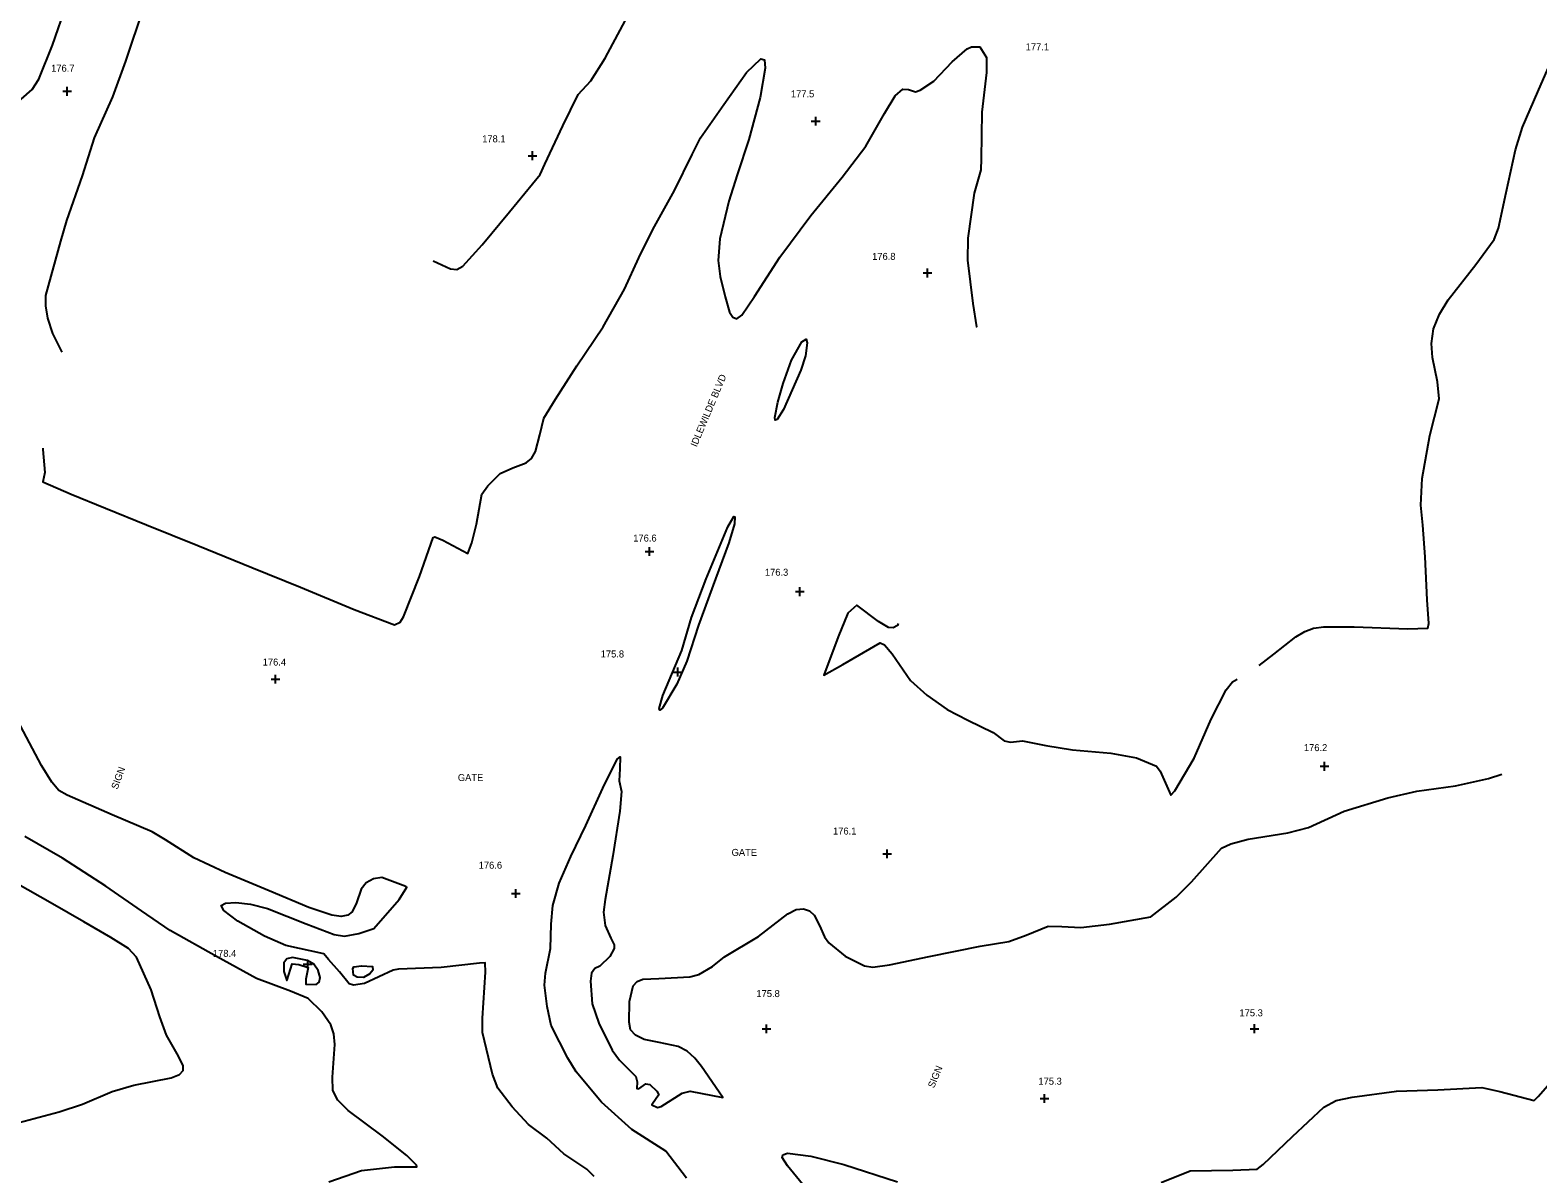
# Model space of a CAD drawing. Extents: x 1467615 to 2003689, y 770235 to 1108726.
# Drawn here: x 1997129.8 to 1997561.1, y 776158.5 to 776485.6 of the extents above; entities that cross this region are included whole.
import ezdxf

# ---------------------------------------------------------------- set-up
doc = ezdxf.new("R2010")
doc.units = 0
for name, color, linetype in [('RD_DTM_Major1', 7, 'Continuous'), ('RD_DTM_Minor1', 7, 'Continuous'), ('RD_DTM_Spot_Elev', 7, 'Continuous'), ('RD_TX_Misc1', 7, 'Continuous')]:
    doc.layers.add(name, color=color, linetype=linetype)

msp = doc.modelspace()

# ---------------------------------------------------------------- linework, layer by layer
at = {"layer": 'RD_DTM_Major1'}
for points in [[(1997453.38, 776156.03), (1997461.66, 776159.38), (1997473.82, 776159.52), (1997480.8, 776159.8), (1997482.56, 776161.17), (1997490.9, 776169.14), (1997499.88, 776177.51), (1997503.42, 776179.5), (1997508.01, 776180.4), (1997520.68, 776182.12), (1997532.49, 776182.47), (1997545.09, 776183.14), (1997550.2, 776182), (1997560, 776179.46), (1997561.18, 776180.58), (1997567.24, 776187.59), (1997569.53, 776189.42), (1997574.48, 776191.66), (1997584.08, 776194.29)], [(1997354.15, 776151.35), (1997346.5, 776160.76), (1997344.91, 776163.13), (1997345.11, 776163.96), (1997346.48, 776164.35), (1997353.14, 776163.53), (1997362.62, 776161.17), (1997377.91, 776156.18)]]:
    msp.add_lwpolyline(points, dxfattribs=at)
at = {"layer": 'RD_DTM_Minor1'}
for points in [[(1997286.62, 776467.18), (1997290.23, 776471.12), (1997294.31, 776477.55), (1997302.2, 776492.37), (1997309.65, 776506.51), (1997313.41, 776514.39), (1997315.15, 776520.48), (1997315.7, 776526.34), (1997315.67, 776530.4), (1997315.28, 776532.17), (1997314.46, 776533.54), (1997311.48, 776535), (1997308.11, 776536.27), (1997304.64, 776538.75), (1997301.04, 776540.1), (1997294.91, 776541.22), (1997293.99, 776541.28)], [(1997124.86, 776463.78), (1997130.45, 776468.61), (1997132.32, 776471.57), (1997136.22, 776481.27), (1997140.31, 776493.1)], [(1997162.25, 776492.06), (1997157.13, 776476.73), (1997153.41, 776466.58), (1997148.14, 776454.85), (1997144.74, 776443.91), (1997140.2, 776431.16), (1997138.57, 776425.27), (1997134.24, 776409.69), (1997134.25, 776406.77), (1997134.83, 776403.21), (1997136.28, 776398.84), (1997138.93, 776393.49)], [(1997133.44, 776366.01), (1997133.47, 776365.69), (1997134.07, 776359.08), (1997133.52, 776356.37), (1997141.61, 776352.86), (1997151.35, 776348.88), (1997163.16, 776344.1), (1997177.79, 776338.2), (1997193.25, 776331.94), (1997207.18, 776326.25), (1997222.48, 776319.91), (1997234.1, 776315.5), (1997235.72, 776316.27), (1997236.67, 776317.79), (1997241.19, 776329.31), (1997245.07, 776340.49), (1997245.58, 776340.64), (1997247.86, 776339.76), (1997255.08, 776335.88), (1997256.18, 776338.92), (1997257.47, 776344.26), (1997259, 776352.88), (1997260.77, 776355.23), (1997264.31, 776358.76), (1997267.87, 776360.45), (1997271.7, 776361.81), (1997273.26, 776363.1), (1997274.39, 776365.06), (1997275.65, 776369.86), (1997276.77, 776374.65), (1997280.07, 776380.09), (1997286.17, 776389.57), (1997293.76, 776400.78), (1997299.81, 776411.55), (1997303.93, 776420.44), (1997307.95, 776428.6), (1997314.11, 776439.7), (1997319.2, 776450.04), (1997321.54, 776454.77), (1997328.24, 776464.32), (1997334.74, 776473.47), (1997338.79, 776477.42), (1997339.9, 776477.1), (1997340.1, 776474.69), (1997338.67, 776466.32), (1997335.42, 776454.31), (1997332.08, 776444.18), (1997329.64, 776436.72), (1997327.15, 776425.93), (1997326.62, 776419.72), (1997327.17, 776415.17), (1997328.66, 776409.34), (1997329.86, 776404.97), (1997330.81, 776403.47), (1997332, 776403.07), (1997333.44, 776404.1), (1997337.05, 776409.43), (1997344.23, 776420.66), (1997353.14, 776432.55), (1997362.13, 776443.59), (1997368.84, 776452.47), (1997374.25, 776461.8), (1997377.22, 776466.82), (1997379.41, 776468.77), (1997381.04, 776468.68), (1997383.07, 776468.01), (1997384.45, 776468.49), (1997388.33, 776471.06), (1997393.55, 776476.56), (1997397.83, 776480.23), (1997399.06, 776480.84), (1997401.51, 776480.84), (1997403.34, 776477.78), (1997403.34, 776473.5), (1997402.08, 776462.13), (1997401.9, 776448.83), (1997401.77, 776445.61), (1997399.86, 776438.96), (1997398, 776426.15), (1997397.98, 776419.82), (1997399.43, 776407.45), (1997400.57, 776400.78), (1997400.63, 776400.66)], [(1997481.35, 776303.87), (1997485.57, 776307.08), (1997491.85, 776312.07), (1997494.43, 776313.65), (1997496.94, 776314.57), (1997499.85, 776314.98), (1997508.58, 776314.96), (1997523.87, 776314.35), (1997529.66, 776314.53), (1997529.86, 776315.89), (1997529.41, 776322.7), (1997528.81, 776334.99), (1997528.15, 776344.04), (1997527.62, 776349.77), (1997528.02, 776357.36), (1997530.17, 776369.66), (1997532.88, 776380.2), (1997532.41, 776385.02), (1997530.99, 776391.94), (1997530.71, 776395.96), (1997531.27, 776400.16), (1997532.94, 776404.4), (1997535.41, 776408.52), (1997543.31, 776418.6), (1997548.55, 776425.72), (1997549.78, 776429), (1997551.99, 776439.16), (1997554.69, 776451.4), (1997556.65, 776457.87), (1997561.05, 776468), (1997566.98, 776481.47)], [(1997245.13, 776419.63), (1997250.1, 776417.34), (1997251.89, 776417.18), (1997253.6, 776418.14), (1997259.09, 776424.17), (1997266.99, 776433.61), (1997275.68, 776444.34), (1997277.01, 776447.24), (1997282.22, 776458.21), (1997286.62, 776467.18)], [(1997345.18, 776384.57), (1997347.6, 776391.21), (1997350.52, 776396.42), (1997351.8, 776397.27), (1997352.06, 776396.14), (1997351.6, 776392.49), (1997350.24, 776388.31), (1997345.35, 776377.06), (1997343.49, 776374.24), (1997342.95, 776374.03), (1997342.8, 776374.82), (1997343.69, 776379.23), (1997345.18, 776384.57)], [(1997310.68, 776291.69), (1997309.97, 776291.14), (1997309.75, 776291.59), (1997310.8, 776295.31), (1997316.25, 776308.16), (1997319.05, 776317.58), (1997323.22, 776328.69), (1997329.44, 776343.57), (1997331.12, 776346.46), (1997331.4, 776346.38), (1997331.26, 776344.43), (1997329.73, 776338.96), (1997325.89, 776328.65), (1997321.02, 776315.42), (1997317.66, 776305.12), (1997314.82, 776298.57), (1997310.68, 776291.69)], [(1997378.11, 776315.93), (1997377.88, 776315.32), (1997376.71, 776314.66), (1997375.36, 776314.78), (1997372.45, 776316.43), (1997366.3, 776321.11), (1997363.71, 776318.82), (1997360.91, 776312.1), (1997356.88, 776301.1), (1997362.28, 776304.17), (1997372.93, 776310.36), (1997374.18, 776309.77), (1997376.43, 776307.2), (1997381.68, 776299.55), (1997386.27, 776295.43), (1997392.12, 776291.33), (1997398.01, 776288.27), (1997405.32, 776284.76), (1997408.4, 776282.37), (1997410.24, 776281.91), (1997413.7, 776282.29), (1997420.34, 776281.01), (1997427.95, 776279.76), (1997438.95, 776278.82), (1997446.27, 776277.49), (1997451.99, 776275.07), (1997453.1, 776273.62), (1997456.08, 776266.77), (1997457.27, 776268.01), (1997462.81, 776277.33), (1997467.64, 776288.51), (1997471.96, 776296.96), (1997473.76, 776299.23), (1997475.06, 776300)], [(1997291.18, 776157.75), (1997289.08, 776159.86), (1997282.45, 776164.18), (1997277.65, 776168.68), (1997272.35, 776172.61), (1997267.72, 776177.67), (1997263.61, 776183.01), (1997262.11, 776187.02), (1997259.24, 776198.89), (1997259.19, 776203.04), (1997260.05, 776216.16), (1997259.95, 776218.88), (1997258.41, 776218.73), (1997247.41, 776217.51), (1997235.24, 776217.02), (1997233.63, 776216.75), (1997225.47, 776212.91), (1997222.37, 776212.47), (1997221.05, 776212.84), (1997218.34, 776216.26), (1997215.17, 776219.76), (1997213.87, 776221.45), (1997203.01, 776223.83), (1997196.9, 776226.43), (1997189.27, 776230.74), (1997185.23, 776233.85), (1997184.51, 776235.25), (1997185.74, 776235.93), (1997188.68, 776236.06), (1997192.88, 776235.62), (1997197.69, 776234.39), (1997208.75, 776229.98), (1997216.78, 776226.96), (1997219.77, 776226.42), (1997223.81, 776227.18), (1997228.16, 776228.7), (1997235.38, 776236.97), (1997237.55, 776240.44), (1997237.34, 776240.64), (1997230.43, 776243.24), (1997228.03, 776242.87), (1997226, 776241.67), (1997224.53, 776239.89), (1997223.18, 776236), (1997221.97, 776233.45), (1997220.74, 776232.5), (1997218.85, 776232.13), (1997216.16, 776232.5), (1997209.59, 776234.7), (1997198.18, 776239.39), (1997185.66, 776244.64), (1997176.65, 776248.87), (1997168.56, 776253.99), (1997164.71, 776256.33), (1997153.32, 776261.17), (1997140.46, 776266.76), (1997138.05, 776268.16), (1997136.04, 776270.52), (1997133.05, 776275.26), (1997126.25, 776288.27)], [(1997317.61, 776157.22), (1997311.65, 776164.96), (1997301.91, 776171.18), (1997293.24, 776179), (1997285.99, 776187.63), (1997283.59, 776191.52), (1997278.9, 776200.87), (1997277.77, 776206.37), (1997276.94, 776212.46), (1997277.28, 776215.88), (1997278.64, 776222.89), (1997278.89, 776229.94), (1997279.32, 776235.2), (1997281.13, 776241.64), (1997284.53, 776249.29), (1997288.8, 776258.12), (1997293.62, 776268.76), (1997297.77, 776277.05), (1997298.59, 776277.75), (1997298.48, 776274.34), (1997298.32, 776270.92), (1997299.03, 776267.86), (1997298.52, 776262.26), (1997296.48, 776249.4), (1997294.31, 776236.95), (1997293.8, 776233.31), (1997294.31, 776229.49), (1997295.91, 776225.89), (1997296.9, 776223.96), (1997296.91, 776222.93), (1997295.66, 776220.64), (1997292.8, 776217.92), (1997291.36, 776217.22), (1997290.36, 776215.86), (1997290.08, 776213.63), (1997290.64, 776207.15), (1997292.5, 776201.61), (1997296.36, 776193.88), (1997298.43, 776191), (1997303.13, 776186.29), (1997303.48, 776184.78), (1997303.41, 776182.85), (1997303.92, 776182.76), (1997305.91, 776184.27), (1997307.06, 776184.07), (1997309.13, 776182.15), (1997309.62, 776181.1), (1997308.89, 776180.01), (1997307.65, 776178.26), (1997309.31, 776177.46), (1997310.35, 776177.73), (1997316.36, 776181.56), (1997318.67, 776182.14), (1997328, 776180.28), (1997321.82, 776189.14), (1997319.94, 776191.6), (1997317.74, 776193.6), (1997315.18, 776194.88), (1997309.76, 776196.02), (1997305.45, 776196.87), (1997302.95, 776198.12), (1997301.55, 776199.66), (1997301.17, 776201.88), (1997301.24, 776207.81), (1997302.33, 776212.23), (1997303.49, 776213.5), (1997305.09, 776214.14), (1997309.62, 776214.4), (1997318.5, 776214.87), (1997321.13, 776215.51), (1997325.02, 776217.8), (1997328.44, 776220.59), (1997338.19, 776226.36), (1997346.55, 776232.81), (1997348.99, 776234.06), (1997351.07, 776234.29), (1997352.77, 776233.68), (1997354.1, 776232.51), (1997355.66, 776229.53), (1997357, 776226.31), (1997358.32, 776224.51), (1997362.98, 776220.7), (1997368.47, 776218.01), (1997370.83, 776217.59), (1997375.62, 776218.27), (1997387.03, 776220.67), (1997401.58, 776223.58), (1997409.74, 776224.97), (1997414.77, 776226.75), (1997421.04, 776229.35), (1997424.89, 776229.27), (1997430.38, 776228.96), (1997438.56, 776229.86), (1997450.35, 776232.02), (1997457.65, 776237.65), (1997462, 776242), (1997470.58, 776251.67), (1997473.31, 776252.91), (1997478.23, 776254.19), (1997489.53, 776256.05), (1997495.51, 776257.56), (1997505.73, 776262.19), (1997518.14, 776266.05), (1997526.49, 776267.95), (1997537.48, 776269.43), (1997546.92, 776271.57), (1997550.81, 776272.82)], [(1997215.27, 776156.21), (1997224.63, 776159.41), (1997234.03, 776160.5), (1997240.48, 776160.45), (1997240.38, 776160.98), (1997237.58, 776163.7), (1997230.52, 776169.37), (1997220.81, 776176.63), (1997217.81, 776179.55), (1997216.4, 776182.27), (1997216.33, 776186.15), (1997217.02, 776195.47), (1997216.71, 776198.54), (1997215.85, 776201.11), (1997213.29, 776204.83), (1997209.41, 776208.6), (1997204.35, 776210.73), (1997194.63, 776214.37), (1997183.13, 776220.67), (1997169.87, 776228.08), (1997161.73, 776233.72), (1997151.46, 776240.79), (1997139.11, 776248.81), (1997128.36, 776255.01)], [(1997126.69, 776173.15), (1997138.15, 776176.2), (1997144.8, 776178.45), (1997153.34, 776182.07), (1997159.49, 776183.81), (1997170.19, 776185.93), (1997172.53, 776186.86), (1997173.6, 776188.05), (1997173.62, 776189.47), (1997171.89, 776192.76), (1997168.8, 776198.12), (1997166.92, 776203.37), (1997164.43, 776211.15), (1997160.22, 776220.41), (1997157.93, 776222.94), (1997152.93, 776226.08), (1997145.16, 776230.56), (1997136.26, 776235.7), (1997125.68, 776241.75)], [(1997203.39, 776214.01), (1997204.79, 776218.58), (1997206.7, 776218.39), (1997209.38, 776217.5), (1997208.68, 776214.13), (1997208.7, 776212.76), (1997211.64, 776212.6), (1997212.53, 776213.27), (1997212.77, 776214.63), (1997212.24, 776216.6), (1997210.99, 776218.45), (1997209.17, 776219.52), (1997204.91, 776220.32), (1997203.26, 776220.02), (1997202.45, 776218.82), (1997202.36, 776216.4), (1997203.25, 776213.76), (1997203.39, 776214.01)], [(1997227, 776215.65), (1997225.17, 776214.66), (1997223.39, 776214.72), (1997222.29, 776215.27), (1997222.12, 776217.21), (1997222.41, 776217.71), (1997224.65, 776218.01), (1997227.77, 776217.76), (1997227.89, 776216.77), (1997227, 776215.65)]]:
    msp.add_lwpolyline(points, dxfattribs=at)
at = {"layer": 'RD_DTM_Spot_Elev'}
for p, q in [((1997139.22, 776468.12), (1997141.72, 776468.12)), ((1997140.47, 776466.87), (1997140.47, 776469.37)), ((1997353.28, 776459.61), (1997355.78, 776459.61)), ((1997354.53, 776458.36), (1997354.53, 776460.86)), ((1997272.31, 776449.7), (1997274.81, 776449.7)), ((1997273.56, 776448.45), (1997273.56, 776450.95)), ((1997385.28, 776416.15), (1997387.78, 776416.15)), ((1997386.53, 776414.9), (1997386.53, 776417.4)), ((1997305.77, 776336.47), (1997308.27, 776336.47)), ((1997307.02, 776335.22), (1997307.02, 776337.72)), ((1997348.75, 776325), (1997351.25, 776325)), ((1997350, 776323.75), (1997350, 776326.25)), ((1997313.8, 776302.02), (1997316.3, 776302.02)), ((1997315.05, 776300.77), (1997315.05, 776303.27)), ((1997198.75, 776300), (1997201.25, 776300)), ((1997200, 776298.75), (1997200, 776301.25)), ((1997500.05, 776273.79), (1997500.05, 776276.29)), ((1997498.8, 776275.04), (1997501.3, 776275.04)), ((1997375, 776248.75), (1997375, 776251.25)), ((1997373.75, 776250), (1997376.25, 776250)), ((1997267.49, 776238.64), (1997269.99, 776238.64)), ((1997268.74, 776237.39), (1997268.74, 776239.89)), ((1997207.98, 776218.42), (1997210.48, 776218.42)), ((1997209.23, 776217.17), (1997209.23, 776219.67)), ((1997339.22, 776199.97), (1997341.72, 776199.97)), ((1997340.47, 776198.72), (1997340.47, 776201.22)), ((1997478.75, 776200), (1997481.25, 776200)), ((1997480, 776198.75), (1997480, 776201.25)), ((1997420, 776178.75), (1997420, 776181.25)), ((1997418.75, 776180), (1997421.25, 776180))]:
    msp.add_line(p, q, dxfattribs=at)

# ---------------------------------------------------------------- texts
for s, p in [('177.1', (1997414.58, 776479.84)), ('176.7', (1997135.85, 776473.72)), ('177.5', (1997347.43, 776466.38)), ('178.1', (1997259.13, 776453.54)), ('176.8', (1997370.67, 776419.9)), ('176.6', (1997302.34, 776339.33)), ('176.3', (1997339.99, 776329.55)), ('175.8', (1997293.03, 776306.18)), ('176.4', (1997196.36, 776303.86)), ('176.2', (1997494.16, 776279.39)), ('176.1', (1997359.48, 776255.53)), ('176.6', (1997258.14, 776245.75)), ('178.4', (1997182.11, 776220.54)), ('175.8', (1997337.57, 776209.04)), ('175.3', (1997475.73, 776203.54)), ('175.3', (1997418.23, 776183.97))]:
    msp.add_text(s, height=2, dxfattribs=at).set_placement(p)
at = {"layer": 'RD_TX_Misc1'}
for s, rotation, p in [('IDLEWILDE BLVD', 67.238, (1997320.48, 776366.24)), ('SIGN', 69.984, (1997154.84, 776268.3)), ('SIGN', 67.7824, (1997388.38, 776182.85))]:
    msp.add_text(s, height=2, rotation=rotation, dxfattribs=at).set_placement(p)
for p in [(1997252.18, 776270.83), (1997330.48, 776249.42)]:
    msp.add_text('GATE', height=2, dxfattribs=at).set_placement(p)

doc.saveas('drawing.dxf')
